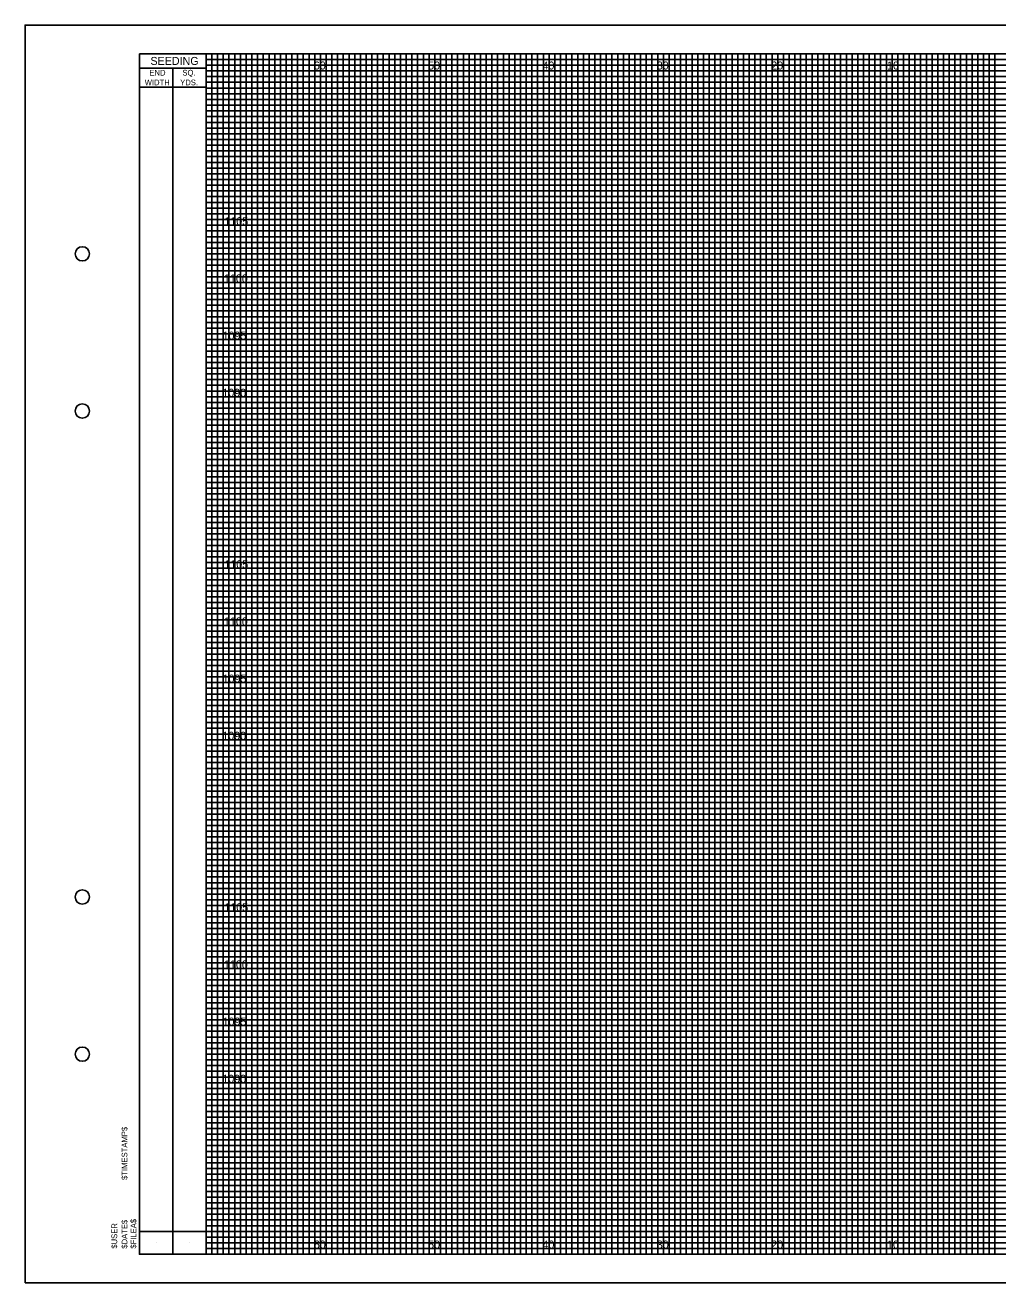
# Model space of a CAD drawing. Extents: x 0 to 170, y 0 to 110.
# Drawn here: x 0 to 85.1, y 0 to 110 of the extents above; entities that cross this region are included whole.
import ezdxf

# ---------------------------------------------------------------- set-up
doc = ezdxf.new("R2010")
doc.units = 0
for name, color, linetype in [('SH_Border', 7, 'Continuous'), ('SH_Cut_Line', 7, 'Continuous'), ('SH_Data', 7, 'Continuous'), ('SH_Major_Grid_Line', 7, 'Continuous'), ('SH_Minor_Grid_Line', 7, 'Continuous'), ('SH_Text', 7, 'Continuous')]:
    doc.layers.add(name, color=color, linetype=linetype)

msp = doc.modelspace()

# ---------------------------------------------------------------- linework, layer by layer
at = {"layer": 'SH_Border'}
msp.add_lwpolyline([(10, 107.5), (167.5, 107.5), (167.5, 2.5), (10, 2.5)], close=True, dxfattribs=at)
for centre in [(5, 90), (5, 76.25), (5, 33.75), (5, 20)]:
    msp.add_circle(centre, 0.625, dxfattribs=at)
at = {"layer": 'SH_Cut_Line'}
msp.add_lwpolyline([(0, 0), (170, 0), (170, 110), (0, 110)], close=True, dxfattribs=at)
at = {"layer": 'SH_Data'}
for p, q in [((15.83, 2.5), (15.83, 107.5)), ((15.83, 106.25), (10, 106.25)), ((12.92, 2.5), (12.92, 106.25)), ((15.83, 104.58), (10, 104.58)), ((10, 4.5), (15.83, 4.5)), ((11.46, 3.53), (11.46, 3.53)), ((14.37, 3.53), (14.37, 3.53))]:
    msp.add_line(p, q, dxfattribs=at)
at = {"layer": 'SH_Major_Grid_Line'}
for p, q in [((20.83, 2.5), (20.83, 107.5)), ((25.83, 2.5), (25.83, 107.5)), ((30.83, 2.5), (30.83, 107.5)), ((35.83, 2.5), (35.83, 107.5)), ((40.83, 2.5), (40.83, 107.5)), ((45.83, 2.5), (45.83, 107.5)), ((50.83, 2.5), (50.83, 107.5)), ((55.83, 2.5), (55.83, 107.5)), ((60.83, 2.5), (60.83, 107.5)), ((65.83, 2.5), (65.83, 107.5)), ((70.83, 2.5), (70.83, 107.5)), ((75.83, 2.5), (75.83, 107.5)), ((80.83, 2.5), (80.83, 107.5)), ((15.83, 102.5), (150.83, 102.5)), ((15.83, 97.5), (150.83, 97.5)), ((15.83, 92.5), (150.83, 92.5)), ((15.83, 87.5), (150.83, 87.5)), ((15.83, 82.5), (150.83, 82.5)), ((15.83, 77.5), (150.83, 77.5)), ((15.83, 72.5), (150.83, 72.5)), ((15.83, 67.5), (150.83, 67.5)), ((15.83, 62.5), (150.83, 62.5)), ((15.83, 57.5), (150.83, 57.5)), ((15.83, 52.5), (150.83, 52.5)), ((15.83, 47.5), (150.83, 47.5)), ((15.83, 42.5), (150.83, 42.5)), ((15.83, 37.5), (150.83, 37.5)), ((15.83, 32.5), (150.83, 32.5)), ((15.83, 27.5), (150.83, 27.5)), ((15.83, 22.5), (150.83, 22.5)), ((15.83, 17.5), (150.83, 17.5)), ((15.83, 12.5), (150.83, 12.5)), ((15.83, 7.5), (150.83, 7.5))]:
    msp.add_line(p, q, dxfattribs=at)
at = {"layer": 'SH_Minor_Grid_Line'}
for p, q in [((15.83, 107), (150.83, 107)), ((16.33, 2.5), (16.33, 107.5)), ((16.83, 2.5), (16.83, 107.5)), ((17.33, 2.5), (17.33, 107.5)), ((17.83, 2.5), (17.83, 107.5)), ((18.33, 2.5), (18.33, 107.5)), ((18.83, 2.5), (18.83, 107.5)), ((19.33, 2.5), (19.33, 107.5)), ((19.83, 2.5), (19.83, 107.5)), ((20.33, 2.5), (20.33, 107.5)), ((21.33, 2.5), (21.33, 107.5)), ((21.83, 2.5), (21.83, 107.5)), ((22.33, 2.5), (22.33, 107.5)), ((22.83, 2.5), (22.83, 107.5)), ((23.33, 2.5), (23.33, 107.5)), ((23.83, 2.5), (23.83, 107.5)), ((24.33, 2.5), (24.33, 107.5)), ((24.83, 2.5), (24.83, 107.5)), ((25.33, 2.5), (25.33, 107.5)), ((26.33, 2.5), (26.33, 107.5)), ((26.83, 2.5), (26.83, 107.5)), ((27.33, 2.5), (27.33, 107.5)), ((27.83, 2.5), (27.83, 107.5)), ((28.33, 2.5), (28.33, 107.5)), ((28.83, 2.5), (28.83, 107.5)), ((29.33, 2.5), (29.33, 107.5)), ((29.83, 2.5), (29.83, 107.5)), ((30.33, 2.5), (30.33, 107.5)), ((31.33, 2.5), (31.33, 107.5)), ((31.83, 2.5), (31.83, 107.5)), ((32.33, 2.5), (32.33, 107.5)), ((32.83, 2.5), (32.83, 107.5)), ((33.33, 2.5), (33.33, 107.5)), ((33.83, 2.5), (33.83, 107.5)), ((34.33, 2.5), (34.33, 107.5)), ((34.83, 2.5), (34.83, 107.5)), ((35.33, 2.5), (35.33, 107.5)), ((36.33, 2.5), (36.33, 107.5)), ((36.83, 2.5), (36.83, 107.5)), ((37.33, 2.5), (37.33, 107.5)), ((37.83, 2.5), (37.83, 107.5)), ((38.33, 2.5), (38.33, 107.5)), ((38.83, 2.5), (38.83, 107.5)), ((39.33, 2.5), (39.33, 107.5)), ((39.83, 2.5), (39.83, 107.5)), ((40.33, 2.5), (40.33, 107.5)), ((41.33, 2.5), (41.33, 107.5)), ((41.83, 2.5), (41.83, 107.5)), ((42.33, 2.5), (42.33, 107.5)), ((42.83, 2.5), (42.83, 107.5)), ((43.33, 2.5), (43.33, 107.5)), ((43.83, 2.5), (43.83, 107.5)), ((44.33, 2.5), (44.33, 107.5)), ((44.83, 2.5), (44.83, 107.5)), ((45.33, 2.5), (45.33, 107.5)), ((46.33, 2.5), (46.33, 107.5)), ((46.83, 2.5), (46.83, 107.5)), ((47.33, 2.5), (47.33, 107.5)), ((47.83, 2.5), (47.83, 107.5)), ((48.33, 2.5), (48.33, 107.5)), ((48.83, 2.5), (48.83, 107.5)), ((49.33, 2.5), (49.33, 107.5)), ((49.83, 2.5), (49.83, 107.5)), ((50.33, 2.5), (50.33, 107.5)), ((51.33, 2.5), (51.33, 107.5)), ((51.83, 2.5), (51.83, 107.5)), ((52.33, 2.5), (52.33, 107.5)), ((52.83, 2.5), (52.83, 107.5)), ((53.33, 2.5), (53.33, 107.5)), ((53.83, 2.5), (53.83, 107.5)), ((54.33, 2.5), (54.33, 107.5)), ((54.83, 2.5), (54.83, 107.5)), ((55.33, 2.5), (55.33, 107.5)), ((56.33, 2.5), (56.33, 107.5)), ((56.83, 2.5), (56.83, 107.5)), ((57.33, 2.5), (57.33, 107.5)), ((57.83, 2.5), (57.83, 107.5)), ((58.33, 2.5), (58.33, 107.5)), ((58.83, 2.5), (58.83, 107.5)), ((59.33, 2.5), (59.33, 107.5)), ((59.83, 2.5), (59.83, 107.5)), ((60.33, 2.5), (60.33, 107.5)), ((61.33, 2.5), (61.33, 107.5)), ((61.83, 2.5), (61.83, 107.5)), ((62.33, 2.5), (62.33, 107.5)), ((62.83, 2.5), (62.83, 107.5)), ((63.33, 2.5), (63.33, 107.5)), ((63.83, 2.5), (63.83, 107.5)), ((64.33, 2.5), (64.33, 107.5)), ((64.83, 2.5), (64.83, 107.5)), ((65.33, 2.5), (65.33, 107.5)), ((66.33, 2.5), (66.33, 107.5)), ((66.83, 2.5), (66.83, 107.5)), ((67.33, 2.5), (67.33, 107.5)), ((67.83, 2.5), (67.83, 107.5)), ((68.33, 2.5), (68.33, 107.5)), ((68.83, 2.5), (68.83, 107.5)), ((69.33, 2.5), (69.33, 107.5)), ((69.83, 2.5), (69.83, 107.5)), ((70.33, 2.5), (70.33, 107.5)), ((71.33, 2.5), (71.33, 107.5)), ((71.83, 2.5), (71.83, 107.5)), ((72.33, 2.5), (72.33, 107.5)), ((72.83, 2.5), (72.83, 107.5)), ((73.33, 2.5), (73.33, 107.5)), ((73.83, 2.5), (73.83, 107.5)), ((74.33, 2.5), (74.33, 107.5)), ((74.83, 2.5), (74.83, 107.5)), ((75.33, 2.5), (75.33, 107.5)), ((76.33, 2.5), (76.33, 107.5)), ((76.83, 2.5), (76.83, 107.5)), ((77.33, 2.5), (77.33, 107.5)), ((77.83, 2.5), (77.83, 107.5)), ((78.33, 2.5), (78.33, 107.5)), ((78.83, 2.5), (78.83, 107.5)), ((79.33, 2.5), (79.33, 107.5)), ((79.83, 2.5), (79.83, 107.5)), ((80.33, 2.5), (80.33, 107.5)), ((81.33, 2.5), (81.33, 107.5)), ((81.83, 2.5), (81.83, 107.5)), ((82.33, 2.5), (82.33, 107.5)), ((82.83, 2.5), (82.83, 107.5)), ((83.33, 2.5), (83.33, 107.5)), ((83.83, 2.5), (83.83, 107.5)), ((84.33, 2.5), (84.33, 107.5)), ((84.83, 2.5), (84.83, 107.5)), ((15.83, 106.5), (150.83, 106.5)), ((15.83, 106), (150.83, 106)), ((15.83, 105.5), (150.83, 105.5)), ((15.83, 105), (150.83, 105)), ((15.83, 104.5), (150.83, 104.5)), ((15.83, 104), (150.83, 104)), ((15.83, 103.5), (150.83, 103.5)), ((15.83, 103), (150.83, 103)), ((15.83, 102), (150.83, 102)), ((15.83, 101.5), (150.83, 101.5)), ((15.83, 101), (150.83, 101)), ((15.83, 100.5), (150.83, 100.5)), ((15.83, 100), (150.83, 100)), ((15.83, 99.5), (150.83, 99.5)), ((15.83, 99), (150.83, 99)), ((15.83, 98.5), (150.83, 98.5)), ((15.83, 98), (150.83, 98)), ((15.83, 97), (150.83, 97)), ((15.83, 96.5), (150.83, 96.5)), ((15.83, 96), (150.83, 96)), ((15.83, 95.5), (150.83, 95.5)), ((15.83, 95), (150.83, 95)), ((15.83, 94.5), (150.83, 94.5)), ((15.83, 94), (150.83, 94)), ((15.83, 93.5), (150.83, 93.5)), ((15.83, 93), (150.83, 93)), ((15.83, 92), (150.83, 92)), ((15.83, 91.5), (150.83, 91.5)), ((15.83, 91), (150.83, 91)), ((15.83, 90.5), (150.83, 90.5)), ((15.83, 90), (150.83, 90)), ((15.83, 89.5), (150.83, 89.5)), ((15.83, 89), (150.83, 89)), ((15.83, 88.5), (150.83, 88.5)), ((15.83, 88), (150.83, 88)), ((15.83, 87), (150.83, 87)), ((15.83, 86.5), (150.83, 86.5)), ((15.83, 86), (150.83, 86)), ((15.83, 85.5), (150.83, 85.5)), ((15.83, 85), (150.83, 85)), ((15.83, 84.5), (150.83, 84.5)), ((15.83, 84), (150.83, 84)), ((15.83, 83.5), (150.83, 83.5)), ((15.83, 83), (150.83, 83)), ((15.83, 82), (150.83, 82)), ((15.83, 81.5), (150.83, 81.5)), ((15.83, 81), (150.83, 81)), ((15.83, 80.5), (150.83, 80.5)), ((15.83, 80), (150.83, 80)), ((15.83, 79.5), (150.83, 79.5)), ((15.83, 79), (150.83, 79)), ((15.83, 78.5), (150.83, 78.5)), ((15.83, 78), (150.83, 78)), ((15.83, 77), (150.83, 77)), ((15.83, 76.5), (150.83, 76.5)), ((15.83, 76), (150.83, 76)), ((15.83, 75.5), (150.83, 75.5)), ((15.83, 75), (150.83, 75)), ((15.83, 74.5), (150.83, 74.5)), ((15.83, 74), (150.83, 74)), ((15.83, 73.5), (150.83, 73.5)), ((15.83, 73), (150.83, 73)), ((15.83, 72), (150.83, 72)), ((15.83, 71.5), (150.83, 71.5)), ((15.83, 71), (150.83, 71)), ((15.83, 70.5), (150.83, 70.5)), ((15.83, 70), (150.83, 70)), ((15.83, 69.5), (150.83, 69.5)), ((15.83, 69), (150.83, 69)), ((15.83, 68.5), (150.83, 68.5)), ((15.83, 68), (150.83, 68)), ((15.83, 67), (150.83, 67)), ((15.83, 66.5), (150.83, 66.5)), ((15.83, 66), (150.83, 66)), ((15.83, 65.5), (150.83, 65.5)), ((15.83, 65), (150.83, 65)), ((15.83, 64.5), (150.83, 64.5)), ((15.83, 64), (150.83, 64)), ((15.83, 63.5), (150.83, 63.5)), ((15.83, 63), (150.83, 63)), ((15.83, 62), (150.83, 62)), ((15.83, 61.5), (150.83, 61.5)), ((15.83, 61), (150.83, 61)), ((15.83, 60.5), (150.83, 60.5)), ((15.83, 60), (150.83, 60)), ((15.83, 59.5), (150.83, 59.5)), ((15.83, 59), (150.83, 59)), ((15.83, 58.5), (150.83, 58.5)), ((15.83, 58), (150.83, 58)), ((15.83, 57), (150.83, 57)), ((15.83, 56.5), (150.83, 56.5)), ((15.83, 56), (150.83, 56)), ((15.83, 55.5), (150.83, 55.5)), ((15.83, 55), (150.83, 55)), ((15.83, 54.5), (150.83, 54.5)), ((15.83, 54), (150.83, 54)), ((15.83, 53.5), (150.83, 53.5)), ((15.83, 53), (150.83, 53)), ((15.83, 52), (150.83, 52)), ((15.83, 51.5), (150.83, 51.5)), ((15.83, 51), (150.83, 51)), ((15.83, 50.5), (150.83, 50.5)), ((15.83, 50), (150.83, 50)), ((15.83, 49.5), (150.83, 49.5)), ((15.83, 49), (150.83, 49)), ((15.83, 48.5), (150.83, 48.5)), ((15.83, 48), (150.83, 48)), ((15.83, 47), (150.83, 47)), ((15.83, 46.5), (150.83, 46.5)), ((15.83, 46), (150.83, 46)), ((15.83, 45.5), (150.83, 45.5)), ((15.83, 45), (150.83, 45)), ((15.83, 44.5), (150.83, 44.5)), ((15.83, 44), (150.83, 44)), ((15.83, 43.5), (150.83, 43.5)), ((15.83, 43), (150.83, 43)), ((15.83, 42), (150.83, 42)), ((15.83, 41.5), (150.83, 41.5)), ((15.83, 41), (150.83, 41)), ((15.83, 40.5), (150.83, 40.5)), ((15.83, 40), (150.83, 40)), ((15.83, 39.5), (150.83, 39.5)), ((15.83, 39), (150.83, 39)), ((15.83, 38.5), (150.83, 38.5)), ((15.83, 38), (150.83, 38)), ((15.83, 37), (150.83, 37)), ((15.83, 36.5), (150.83, 36.5)), ((15.83, 36), (150.83, 36)), ((15.83, 35.5), (150.83, 35.5)), ((15.83, 35), (150.83, 35)), ((15.83, 34.5), (150.83, 34.5)), ((15.83, 34), (150.83, 34)), ((15.83, 33.5), (150.83, 33.5)), ((15.83, 33), (150.83, 33)), ((15.83, 32), (150.83, 32)), ((15.83, 31.5), (150.83, 31.5)), ((15.83, 31), (150.83, 31)), ((15.83, 30.5), (150.83, 30.5)), ((15.83, 30), (150.83, 30)), ((15.83, 29.5), (150.83, 29.5)), ((15.83, 29), (150.83, 29)), ((15.83, 28.5), (150.83, 28.5)), ((15.83, 28), (150.83, 28)), ((15.83, 27), (150.83, 27)), ((15.83, 26.5), (150.83, 26.5)), ((15.83, 26), (150.83, 26)), ((15.83, 25.5), (150.83, 25.5)), ((15.83, 25), (150.83, 25)), ((15.83, 24.5), (150.83, 24.5)), ((15.83, 24), (150.83, 24)), ((15.83, 23.5), (150.83, 23.5)), ((15.83, 23), (150.83, 23)), ((15.83, 22), (150.83, 22)), ((15.83, 21.5), (150.83, 21.5)), ((15.83, 21), (150.83, 21)), ((15.83, 20.5), (150.83, 20.5)), ((15.83, 20), (150.83, 20)), ((15.83, 19.5), (150.83, 19.5)), ((15.83, 19), (150.83, 19)), ((15.83, 18.5), (150.83, 18.5)), ((15.83, 18), (150.83, 18)), ((15.83, 17), (150.83, 17)), ((15.83, 16.5), (150.83, 16.5)), ((15.83, 16), (150.83, 16)), ((15.83, 15.5), (150.83, 15.5)), ((15.83, 15), (150.83, 15)), ((15.83, 14.5), (150.83, 14.5)), ((15.83, 14), (150.83, 14)), ((15.83, 13.5), (150.83, 13.5)), ((15.83, 13), (150.83, 13)), ((15.83, 12), (150.83, 12)), ((15.83, 11.5), (150.83, 11.5)), ((15.83, 11), (150.83, 11)), ((15.83, 10.5), (150.83, 10.5)), ((15.83, 10), (150.83, 10)), ((15.83, 9.5), (150.83, 9.5)), ((15.83, 9), (150.83, 9)), ((15.83, 8.5), (150.83, 8.5)), ((15.83, 8), (150.83, 8)), ((15.83, 7), (150.83, 7)), ((15.83, 6.5), (150.83, 6.5)), ((15.83, 6), (150.83, 6)), ((15.83, 5.5), (150.83, 5.5)), ((15.83, 5), (150.83, 5)), ((15.83, 4.5), (150.83, 4.5)), ((15.83, 4), (150.83, 4)), ((15.83, 3.5), (150.83, 3.5)), ((15.83, 3), (150.83, 3))]:
    msp.add_line(p, q, dxfattribs=at)

# ---------------------------------------------------------------- texts
at = {"layer": 'SH_Data'}
for s, height, p in [('SEEDING', 0.7, (10.96, 106.52)), ('END', 0.5, (10.87, 105.59)), ('SQ.', 0.5, (13.75, 105.59)), ('WIDTH', 0.5, (10.46, 104.74)), ('YDS.', 0.5, (13.56, 104.74))]:
    msp.add_text(s, height=height, dxfattribs=at).set_placement(p)
for s, p in [('$TIMESTAMP$', (8.94, 9)), ('$DATE$', (8.94, 2.99)), ('$FILEA$', (9.72, 2.99)), ('$USER', (8.05, 2.99))]:
    msp.add_text(s, height=0.5, rotation=89.9931, dxfattribs=at).set_placement(p)
at = {"layer": 'SH_Text'}
for s, p in [('60', (25.25, 106.12)), ('50', (35.25, 106.12)), ('40', (45.25, 106.12)), ('30', (55.25, 106.12)), ('20', (65.26, 106.12)), ('10', (75.39, 106.12)), ('1105', (17.43, 92.5)), ('1100', (17.39, 87.5)), ('1095', (17.27, 82.5)), ('1090', (17.25, 77.5)), ('1105', (17.43, 62.5)), ('1100', (17.39, 57.5)), ('1095', (17.27, 52.5)), ('1090', (17.25, 47.5)), ('1105', (17.43, 32.5)), ('1100', (17.39, 27.5)), ('1095', (17.27, 22.5)), ('1090', (17.25, 17.5)), ('60', (25.25, 3)), ('50', (35.25, 3)), ('40', (45.25, 3)), ('30', (55.25, 3)), ('20', (65.26, 3)), ('10', (75.39, 3))]:
    msp.add_text(s, height=0.7, dxfattribs=at).set_placement(p)

doc.saveas('drawing.dxf')
